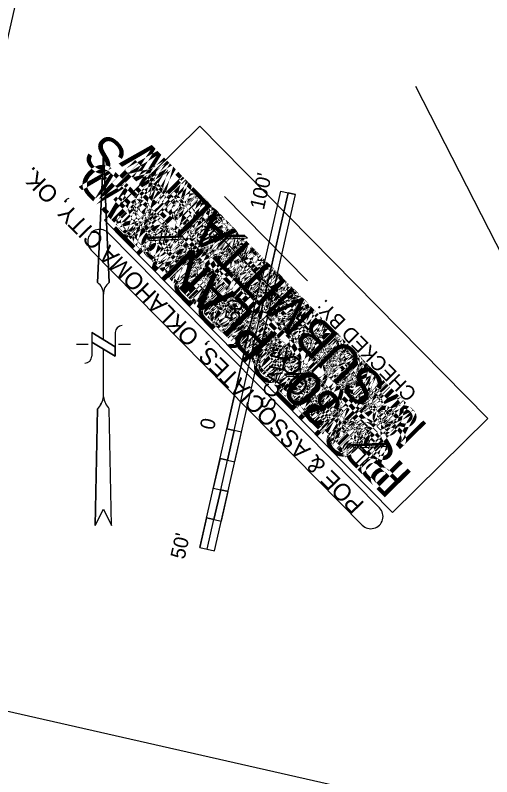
# Model space of a CAD drawing. Extents: x 2149833 to 2151401, y 143015 to 145036.
# Drawn here: x 2149999.9 to 2150195.2, y 143400.5 to 143713 of the extents above; entities that cross this region are included whole.
import ezdxf

# ---------------------------------------------------------------- set-up
doc = ezdxf.new("R2010")
doc.units = 0
for name, color, linetype in [('PR_Align_Ramp_A_Leader', 7, 'Continuous'), ('SHT_North_Arrow', 7, 'Continuous'), ('SHT_Scale', 7, 'Continuous'), ('SHT_Sheet_Border', 7, 'Continuous'), ('SHT_Stamp_30_Submit', 7, 'Continuous'), ('SHT_Stamp_70_Submit', 7, 'Continuous'), ('SHT_Stamp_Check_Print', 7, 'Continuous'), ('SHT_Stamp_Est_Inf', 7, 'Continuous'), ('SHT_Stamp_FFR', 7, 'Continuous'), ('SHT_Stamp_Info_Material', 7, 'Continuous'), ('SHT_Stamp_No_Const', 7, 'Continuous'), ('SHT_Stamp_No_Design', 7, 'Continuous'), ('SHT_Stamp_Plan_Hand', 7, 'Continuous'), ('SHT_Stamp_Pre_Plan', 7, 'Continuous'), ('SHT_Stamp_Ret_Sub', 7, 'Continuous'), ('SHT_Stamp_Rev_Prop_RW', 7, 'Continuous'), ('SHT_Stamp_Rev_Sheet', 7, 'Continuous'), ('SHT_Stamp_RW_Utilities_Meeting', 7, 'Continuous'), ('SHT_Stamp_RW_Utilities_Review', 7, 'Continuous'), ('SHT_Stamp_Send_Comments', 7, 'Continuous')]:
    doc.layers.add(name, color=color, linetype=linetype)

msp = doc.modelspace()

# ---------------------------------------------------------------- linework, layer by layer
at = {"layer": 'PR_Align_Ramp_A_Leader'}
msp.add_lwpolyline([(2150163.96, 143683.88), (2150268.72, 143479.12)], dxfattribs=at)
at = {"layer": 'SHT_North_Arrow'}
for p, q in [((2150033.65, 143603.23), (2150036.05, 143656.12)), ((2150036.05, 143656.12), (2150033.65, 143603.23)), ((2150036.05, 143656.12), (2150038.46, 143603.23)), ((2150038.46, 143603.23), (2150036.05, 143656.12)), ((2150036.05, 143579.84), (2150036.05, 143598.55)), ((2150040.85, 143576.96), (2150031.26, 143582.72)), ((2150031.26, 143582.72), (2150040.85, 143576.96)), ((2150031.26, 143582.72), (2150031.26, 143573.12)), ((2150036.05, 143579.84), (2150031.26, 143582.72)), ((2150031.26, 143582.72), (2150031.26, 143578.88)), ((2150040.85, 143582.72), (2150040.85, 143573.12)), ((2150040.85, 143573.12), (2150031.26, 143578.88)), ((2150040.85, 143576.96), (2150036.05, 143579.84)), ((2150029.82, 143577.92), (2150025.02, 143577.92)), ((2150036.05, 143556.33), (2150036.05, 143576)), ((2150040.85, 143573.12), (2150040.85, 143576.96)), ((2150047.09, 143577.92), (2150042.29, 143577.92)), ((2150032.69, 143503.56), (2150033.65, 143551.53)), ((2150033.65, 143551.53), (2150032.69, 143503.56)), ((2150039.41, 143503.56), (2150038.45, 143551.53)), ((2150039.41, 143503.56), (2150038.45, 143551.53)), ((2150032.69, 143503.56), (2150036.05, 143510.27)), ((2150032.69, 143503.56), (2150036.05, 143510.27)), ((2150036.05, 143510.27), (2150039.41, 143503.56)), ((2150036.05, 143510.27), (2150039.41, 143503.56))]:
    msp.add_line(p, q, dxfattribs=at)
for points in [[(2150031.26, 143578.88), (2150036.05, 143576), (2150040.85, 143573.12)], [(2150036.06, 143556.33), (2150036.05, 143556.33), (2150036.05, 143556.33)]]:
    msp.add_lwpolyline(points, dxfattribs=at)
for centre, radius, start, end in [((2150030.3, 143598.55), 5.76, 0, 54.3802), ((2150030.3, 143598.55), 5.76, 0, 54.3802), ((2150041.81, 143598.55), 5.76, 125.6198, 180), ((2150041.81, 143598.55), 5.76, 125.6198, 180), ((2150043.73, 143582.72), 2.88, 90, 180), ((2150028.38, 143573.12), 2.88, 270, 0), ((2150027.7, 143557.5), 8.43, 314.9567, 352.4189), ((2150027.7, 143557.5), 8.43, 314.9567, 352.059), ((2150044.4, 143557.5), 8.43, 187.5811, 225.0433), ((2150044.4, 143557.5), 8.43, 187.941, 225.0433)]:
    msp.add_arc(centre, radius, start, end, dxfattribs=at)
at = {"layer": 'SHT_Scale'}
for p, q in [((2150075.55, 143494.54), (2150108.75, 143640.82)), ((2150081.64, 143493.16), (2150114.84, 143639.44)), ((2150089.66, 143542.61), (2150111.8, 143640.13)), ((2150111.8, 143640.13), (2150100.73, 143591.37)), ((2150103.78, 143590.68), (2150114.84, 143639.44)), ((2150108.75, 143640.82), (2150111.8, 143640.13)), ((2150111.8, 143640.13), (2150114.84, 143639.44)), ((2150114.84, 143639.44), (2150111.8, 143640.13)), ((2150097.68, 143592.06), (2150086.61, 143543.3)), ((2150089.66, 143542.61), (2150100.73, 143591.37)), ((2150100.73, 143591.37), (2150097.68, 143592.06)), ((2150100.73, 143591.37), (2150097.68, 143592.06)), ((2150103.78, 143590.68), (2150100.73, 143591.37)), ((2150100.73, 143591.37), (2150103.78, 143590.68)), ((2150089.66, 143542.61), (2150086.61, 143543.3)), ((2150086.61, 143543.3), (2150089.66, 143542.61)), ((2150086.89, 143530.42), (2150089.66, 143542.61)), ((2150089.66, 143542.61), (2150086.89, 143530.42)), ((2150092.71, 143541.92), (2150089.66, 143542.61)), ((2150092.71, 143541.92), (2150089.66, 143542.61)), ((2150089.94, 143529.73), (2150092.71, 143541.92)), ((2150083.85, 143531.11), (2150081.08, 143518.92)), ((2150083.85, 143531.11), (2150089.94, 143529.73)), ((2150086.89, 143530.42), (2150083.85, 143531.11)), ((2150084.13, 143518.23), (2150086.89, 143530.42)), ((2150084.13, 143518.23), (2150086.89, 143530.42)), ((2150086.89, 143530.42), (2150089.94, 143529.73)), ((2150081.08, 143518.92), (2150087.18, 143517.54)), ((2150081.08, 143518.92), (2150087.18, 143517.54)), ((2150081.08, 143518.92), (2150084.13, 143518.23)), ((2150081.36, 143506.04), (2150084.13, 143518.23)), ((2150084.13, 143518.23), (2150081.36, 143506.04)), ((2150087.18, 143517.54), (2150084.13, 143518.23)), ((2150084.41, 143505.35), (2150087.18, 143517.54)), ((2150078.31, 143506.73), (2150075.55, 143494.54)), ((2150078.31, 143506.73), (2150084.41, 143505.35)), ((2150081.36, 143506.04), (2150078.31, 143506.73)), ((2150078.59, 143493.85), (2150081.36, 143506.04)), ((2150078.59, 143493.85), (2150081.36, 143506.04)), ((2150081.36, 143506.04), (2150084.41, 143505.35)), ((2150075.55, 143494.54), (2150081.64, 143493.16)), ((2150075.55, 143494.54), (2150078.59, 143493.85))]:
    msp.add_line(p, q, dxfattribs=at)
at = {"layer": 'SHT_Sheet_Border'}
msp.add_lwpolyline([(2151309.68, 144744.32), (2150961.07, 143208.38), (2149937.11, 143440.79), (2150285.72, 144976.72)], close=True, dxfattribs=at)
at = {"layer": 'SHT_Stamp_30_Submit'}
for p, q in [((2150075.62, 143667.47), (2150036.46, 143628.91)), ((2150193.7, 143547.55), (2150075.62, 143667.47)), ((2150154.53, 143508.99), (2150036.46, 143628.91)), ((2150149.25, 143510.8), (2150038.19, 143623.6)), ((2150142.12, 143503.79), (2150031.06, 143616.58)), ((2150121.9, 143566.24), (2150110.3, 143565.73)), ((2150122.17, 143565.96), (2150110.57, 143565.45)), ((2150122.97, 143565.15), (2150121.9, 143566.24)), ((2150111.37, 143564.64), (2150110.3, 143565.73)), ((2150122.35, 143565.79), (2150110.74, 143565.27)), ((2150122.97, 143565.15), (2150111.37, 143564.64)), ((2150193.7, 143547.55), (2150154.53, 143508.99))]:
    msp.add_line(p, q, dxfattribs=at)
for centre, start, end in [((2150034.6, 143620.09), 44.5567, 224.5615), ((2150145.67, 143507.29), 224.5519, 44.5567)]:
    msp.add_arc(centre, 5, start, end, dxfattribs=at)
at = {"layer": 'SHT_Stamp_70_Submit'}
for p, q in [((2150075.62, 143667.47), (2150036.46, 143628.91)), ((2150193.7, 143547.55), (2150075.62, 143667.47)), ((2150154.53, 143508.99), (2150036.46, 143628.91)), ((2150149.25, 143510.8), (2150038.19, 143623.6)), ((2150142.12, 143503.79), (2150031.06, 143616.58)), ((2150121.9, 143566.24), (2150110.3, 143565.73)), ((2150122.17, 143565.96), (2150110.57, 143565.45)), ((2150122.97, 143565.15), (2150121.9, 143566.24)), ((2150111.37, 143564.64), (2150110.3, 143565.73)), ((2150122.35, 143565.79), (2150110.74, 143565.27)), ((2150122.97, 143565.15), (2150111.37, 143564.64)), ((2150193.7, 143547.55), (2150154.53, 143508.99))]:
    msp.add_line(p, q, dxfattribs=at)
for centre, start, end in [((2150034.6, 143620.09), 44.5567, 224.5615), ((2150145.67, 143507.29), 224.5519, 44.5567)]:
    msp.add_arc(centre, 5, start, end, dxfattribs=at)
at = {"layer": 'SHT_Stamp_Check_Print'}
for p, q in [((2150075.62, 143667.47), (2150036.46, 143628.91)), ((2150193.7, 143547.55), (2150075.62, 143667.47)), ((2150119.74, 143603.96), (2150085.7, 143638.54)), ((2150154.53, 143508.99), (2150036.46, 143628.91)), ((2150110.64, 143595), (2150076.6, 143629.57)), ((2150149.25, 143510.8), (2150038.19, 143623.6)), ((2150142.12, 143503.79), (2150031.06, 143616.58)), ((2150193.7, 143547.55), (2150154.53, 143508.99))]:
    msp.add_line(p, q, dxfattribs=at)
for centre, start, end in [((2150034.6, 143620.09), 44.5567, 224.5615), ((2150145.67, 143507.29), 224.5519, 44.5567)]:
    msp.add_arc(centre, 5, start, end, dxfattribs=at)
at = {"layer": 'SHT_Stamp_Est_Inf'}
for p, q in [((2150075.62, 143667.47), (2150036.46, 143628.91)), ((2150193.7, 143547.55), (2150075.62, 143667.47)), ((2150154.53, 143509), (2150036.46, 143628.91)), ((2150149.24, 143510.8), (2150038.19, 143623.6)), ((2150142.12, 143503.79), (2150031.06, 143616.58)), ((2150193.7, 143547.55), (2150154.53, 143509))]:
    msp.add_line(p, q, dxfattribs=at)
for centre, start, end in [((2150034.6, 143620.09), 44.5567, 224.5615), ((2150145.67, 143507.29), 224.5519, 44.5567)]:
    msp.add_arc(centre, 5, start, end, dxfattribs=at)
at = {"layer": 'SHT_Stamp_FFR'}
for p, q in [((2150075.62, 143667.47), (2150036.46, 143628.91)), ((2150193.7, 143547.55), (2150075.62, 143667.47)), ((2150154.53, 143508.99), (2150036.46, 143628.91)), ((2150149.25, 143510.8), (2150038.19, 143623.6)), ((2150142.12, 143503.79), (2150031.06, 143616.58)), ((2150193.7, 143547.55), (2150154.53, 143508.99))]:
    msp.add_line(p, q, dxfattribs=at)
for centre, start, end in [((2150034.6, 143620.09), 44.5567, 224.5615), ((2150145.67, 143507.29), 224.5519, 44.5567)]:
    msp.add_arc(centre, 5, start, end, dxfattribs=at)
at = {"layer": 'SHT_Stamp_Info_Material'}
for p, q in [((2150075.62, 143667.47), (2150036.46, 143628.91)), ((2150193.7, 143547.55), (2150075.62, 143667.47)), ((2150154.53, 143508.99), (2150036.46, 143628.91)), ((2150149.25, 143510.8), (2150038.19, 143623.6)), ((2150142.12, 143503.79), (2150031.06, 143616.58)), ((2150193.7, 143547.55), (2150154.53, 143508.99))]:
    msp.add_line(p, q, dxfattribs=at)
for centre, start, end in [((2150034.6, 143620.09), 44.5567, 224.5615), ((2150145.67, 143507.29), 224.5519, 44.5567)]:
    msp.add_arc(centre, 5, start, end, dxfattribs=at)
at = {"layer": 'SHT_Stamp_No_Const'}
for p, q in [((2150075.62, 143667.47), (2150036.46, 143628.91)), ((2150193.7, 143547.55), (2150075.62, 143667.47)), ((2150154.53, 143508.99), (2150036.46, 143628.91)), ((2150149.25, 143510.8), (2150038.19, 143623.6)), ((2150142.12, 143503.79), (2150031.06, 143616.58)), ((2150193.7, 143547.55), (2150154.53, 143508.99))]:
    msp.add_line(p, q, dxfattribs=at)
for centre, start, end in [((2150034.6, 143620.09), 44.5567, 224.5615), ((2150145.67, 143507.29), 224.5519, 44.5567)]:
    msp.add_arc(centre, 5, start, end, dxfattribs=at)
at = {"layer": 'SHT_Stamp_No_Design'}
for p, q in [((2150075.62, 143667.47), (2150036.46, 143628.91)), ((2150193.7, 143547.55), (2150075.62, 143667.47)), ((2150154.53, 143508.99), (2150036.46, 143628.91)), ((2150149.25, 143510.8), (2150038.19, 143623.6)), ((2150142.12, 143503.79), (2150031.06, 143616.58)), ((2150193.7, 143547.55), (2150154.53, 143508.99))]:
    msp.add_line(p, q, dxfattribs=at)
for centre, start, end in [((2150034.6, 143620.09), 44.5567, 224.5615), ((2150145.67, 143507.29), 224.5519, 44.5567)]:
    msp.add_arc(centre, 5, start, end, dxfattribs=at)
at = {"layer": 'SHT_Stamp_Plan_Hand'}
for p, q in [((2150075.62, 143667.47), (2150036.46, 143628.91)), ((2150193.7, 143547.55), (2150075.62, 143667.47)), ((2150154.53, 143508.99), (2150036.46, 143628.91)), ((2150149.25, 143510.8), (2150038.19, 143623.6)), ((2150142.12, 143503.79), (2150031.06, 143616.58)), ((2150193.7, 143547.55), (2150154.53, 143508.99))]:
    msp.add_line(p, q, dxfattribs=at)
for centre, start, end in [((2150034.6, 143620.09), 44.5567, 224.5615), ((2150145.67, 143507.29), 224.5519, 44.5567)]:
    msp.add_arc(centre, 5, start, end, dxfattribs=at)
at = {"layer": 'SHT_Stamp_Pre_Plan'}
for p, q in [((2150075.62, 143667.47), (2150036.46, 143628.91)), ((2150193.7, 143547.55), (2150075.62, 143667.47)), ((2150154.53, 143508.99), (2150036.46, 143628.91)), ((2150149.25, 143510.8), (2150038.19, 143623.6)), ((2150142.12, 143503.79), (2150031.06, 143616.58)), ((2150193.7, 143547.55), (2150154.53, 143508.99))]:
    msp.add_line(p, q, dxfattribs=at)
for centre, start, end in [((2150034.6, 143620.09), 44.5567, 224.5615), ((2150145.67, 143507.29), 224.5519, 44.5567)]:
    msp.add_arc(centre, 5, start, end, dxfattribs=at)
at = {"layer": 'SHT_Stamp_Ret_Sub'}
for p, q in [((2150075.62, 143667.47), (2150036.46, 143628.91)), ((2150193.7, 143547.55), (2150075.62, 143667.47)), ((2150154.53, 143508.99), (2150036.46, 143628.91)), ((2150149.25, 143510.8), (2150038.19, 143623.6)), ((2150142.12, 143503.79), (2150031.06, 143616.58)), ((2150193.7, 143547.55), (2150154.53, 143508.99))]:
    msp.add_line(p, q, dxfattribs=at)
for centre, start, end in [((2150034.6, 143620.09), 44.5567, 224.5615), ((2150145.67, 143507.29), 224.5519, 44.5567)]:
    msp.add_arc(centre, 5, start, end, dxfattribs=at)
at = {"layer": 'SHT_Stamp_Rev_Prop_RW'}
for p, q in [((2150075.62, 143667.47), (2150036.46, 143628.91)), ((2150193.7, 143547.55), (2150075.62, 143667.47)), ((2150154.53, 143508.99), (2150036.46, 143628.91)), ((2150149.25, 143510.8), (2150038.19, 143623.6)), ((2150093.74, 143622.78), (2150079.41, 143622.15)), ((2150094.07, 143622.44), (2150079.75, 143621.8)), ((2150094.29, 143622.22), (2150079.96, 143621.58)), ((2150095.06, 143621.43), (2150093.74, 143622.78)), ((2150080.73, 143620.8), (2150079.41, 143622.15)), ((2150095.06, 143621.43), (2150080.73, 143620.8)), ((2150142.12, 143503.79), (2150031.06, 143616.58)), ((2150193.7, 143547.55), (2150154.53, 143508.99))]:
    msp.add_line(p, q, dxfattribs=at)
for centre, start, end in [((2150034.6, 143620.09), 44.5567, 224.5615), ((2150145.67, 143507.29), 224.5519, 44.5567)]:
    msp.add_arc(centre, 5, start, end, dxfattribs=at)
at = {"layer": 'SHT_Stamp_Rev_Sheet'}
for p, q in [((2150075.62, 143667.47), (2150036.46, 143628.91)), ((2150193.7, 143547.55), (2150075.62, 143667.47)), ((2150154.53, 143508.99), (2150036.46, 143628.91)), ((2150149.25, 143510.8), (2150038.19, 143623.6)), ((2150142.12, 143503.79), (2150031.06, 143616.58)), ((2150193.7, 143547.55), (2150154.53, 143508.99))]:
    msp.add_line(p, q, dxfattribs=at)
for centre, start, end in [((2150034.6, 143620.09), 44.5567, 224.5615), ((2150145.67, 143507.29), 224.5519, 44.5567)]:
    msp.add_arc(centre, 5, start, end, dxfattribs=at)
at = {"layer": 'SHT_Stamp_RW_Utilities_Meeting'}
for p, q in [((2150075.62, 143667.47), (2150036.46, 143628.91)), ((2150193.7, 143547.55), (2150075.62, 143667.47)), ((2150154.53, 143508.99), (2150036.46, 143628.91)), ((2150149.25, 143510.8), (2150038.19, 143623.6)), ((2150142.12, 143503.79), (2150031.06, 143616.58)), ((2150193.7, 143547.55), (2150154.53, 143508.99)), ((2150151.95, 143537.31), (2150137.63, 143536.68)), ((2150138.95, 143535.33), (2150137.63, 143536.68)), ((2150152.29, 143536.97), (2150137.97, 143536.33)), ((2150152.51, 143536.75), (2150138.18, 143536.11)), ((2150153.28, 143535.96), (2150138.95, 143535.33)), ((2150153.28, 143535.96), (2150151.95, 143537.31))]:
    msp.add_line(p, q, dxfattribs=at)
for centre, start, end in [((2150034.6, 143620.09), 44.5567, 224.5615), ((2150145.67, 143507.29), 224.5519, 44.5567)]:
    msp.add_arc(centre, 5, start, end, dxfattribs=at)
at = {"layer": 'SHT_Stamp_RW_Utilities_Review'}
for p, q in [((2150075.62, 143667.47), (2150036.46, 143628.91)), ((2150193.7, 143547.55), (2150075.62, 143667.47)), ((2150154.53, 143508.99), (2150036.46, 143628.91)), ((2150149.25, 143510.8), (2150038.19, 143623.6)), ((2150068.15, 143622.41), (2150053.83, 143621.78)), ((2150069.48, 143621.07), (2150068.15, 143622.41)), ((2150055.15, 143620.43), (2150053.83, 143621.78)), ((2150068.49, 143622.07), (2150054.17, 143621.44)), ((2150068.71, 143621.85), (2150054.38, 143621.22)), ((2150069.48, 143621.07), (2150055.15, 143620.43)), ((2150142.12, 143503.79), (2150031.06, 143616.58)), ((2150193.7, 143547.55), (2150154.53, 143508.99))]:
    msp.add_line(p, q, dxfattribs=at)
for centre, start, end in [((2150034.6, 143620.09), 44.5567, 224.5615), ((2150145.67, 143507.29), 224.5519, 44.5567)]:
    msp.add_arc(centre, 5, start, end, dxfattribs=at)
at = {"layer": 'SHT_Stamp_Send_Comments'}
for p, q in [((2150075.62, 143667.47), (2150036.46, 143628.91)), ((2150193.7, 143547.55), (2150075.62, 143667.47)), ((2150154.53, 143508.99), (2150036.46, 143628.91)), ((2150149.25, 143510.8), (2150038.19, 143623.6)), ((2150142.12, 143503.79), (2150031.06, 143616.58)), ((2150193.7, 143547.55), (2150154.53, 143508.99))]:
    msp.add_line(p, q, dxfattribs=at)
for centre, start, end in [((2150034.6, 143620.09), 44.5567, 224.5615), ((2150145.67, 143507.29), 224.5519, 44.5567)]:
    msp.add_arc(centre, 5, start, end, dxfattribs=at)

# ---------------------------------------------------------------- texts
at = {"layer": 'SHT_Scale'}
for s, p in [("100'", (2150101.81, 143632.86)), ("50'", (2150091.4, 143586.97)), ('SCALE', (2150105.92, 143550.44)), ('0', (2150081.3, 143542.48)), ("50'", (2150069.26, 143489.45))]:
    msp.add_text(s, height=6, rotation=77.2123, dxfattribs=at).set_placement(p)
at = {"layer": 'SHT_Stamp_30_Submit'}
for s, height, p in [('POE & ASSOCIATES, OKLAHOMA CITY, OK.', 7, (2150143.34, 143512.71)), ('SUBMITTAL', 15, (2150152.73, 143561.33)), ('30   PLAN', 15, (2150135.07, 143553.14)), ('O', 7.65, (2150118.83, 143569.32)), ('O', 7.65, (2150121.16, 143560.95))]:
    msp.add_text(s, height=height, rotation=134.5567, dxfattribs=at).set_placement(p)
at = {"layer": 'SHT_Stamp_70_Submit'}
for s, height, p in [('POE & ASSOCIATES, OKLAHOMA CITY, OK.', 7, (2150143.34, 143512.71)), ('SUBMITTAL', 15, (2150152.73, 143561.33)), ('70   PLAN', 15, (2150135.32, 143552.88)), ('O', 7.65, (2150118.83, 143569.32)), ('O', 7.65, (2150121.16, 143560.95))]:
    msp.add_text(s, height=height, rotation=134.5567, dxfattribs=at).set_placement(p)
at = {"layer": 'SHT_Stamp_Check_Print'}
for s, height, p in [('POE & ASSOCIATES, OKLAHOMA CITY, OK.', 7, (2150143.33, 143512.71)), ('CHECK PRINT', 15, (2150145.79, 143539.16)), ('CHECKED BY:', 6, (2150164.91, 143558.08)), ('REVISED BY:', 6, (2150155.83, 143549.13))]:
    msp.add_text(s, height=height, rotation=134.5567, dxfattribs=at).set_placement(p)
at = {"layer": 'SHT_Stamp_Est_Inf'}
for s, height, p in [('POE & ASSOCIATES, OKLAHOMA CITY, OK.', 7, (2150143.33, 143512.71)), ('INFORMATION', 15, (2150160.4, 143553.54)), ('BASED ON EST.', 15, (2150151.6, 143536.35))]:
    msp.add_text(s, height=height, rotation=134.5567, dxfattribs=at).set_placement(p)
at = {"layer": 'SHT_Stamp_FFR'}
for s, height, p in [('POE & ASSOCIATES, OKLAHOMA CITY, OK.', 7, (2150143.33, 143512.71)), ('FINAL FIELD', 15, (2150143.85, 143544.21)), ('REVIEW', 15, (2150141.92, 143572.31))]:
    msp.add_text(s, height=height, rotation=134.5567, dxfattribs=at).set_placement(p)
at = {"layer": 'SHT_Stamp_Info_Material'}
for s, height, p in [('MATERIAL ONLY', 15, (2150169.47, 143544.33)), ('POE & ASSOCIATES, OKLAHOMA CITY, OK.', 7, (2150143.33, 143512.71)), ('INFORMATION', 15, (2150147.33, 143540.68))]:
    msp.add_text(s, height=height, rotation=134.5567, dxfattribs=at).set_placement(p)
at = {"layer": 'SHT_Stamp_No_Const'}
for s, height, p in [('POE & ASSOCIATES, OKLAHOMA CITY, OK.', 7, (2150143.33, 143512.71)), ('NOT TO BE USED', 15, (2150158.27, 143529.57)), ('FOR CONST.', 15, (2150154.14, 143559.9))]:
    msp.add_text(s, height=height, rotation=134.5567, dxfattribs=at).set_placement(p)
at = {"layer": 'SHT_Stamp_No_Design'}
for s, height, p in [('POE & ASSOCIATES, OKLAHOMA CITY, OK.', 7, (2150143.33, 143512.71)), ('NOT TO BE USED', 15, (2150158.27, 143529.57)), ('FOR DESIGN', 15, (2150154.76, 143559.27))]:
    msp.add_text(s, height=height, rotation=134.5567, dxfattribs=at).set_placement(p)
at = {"layer": 'SHT_Stamp_Plan_Hand'}
for s, height, p in [('POE & ASSOCIATES, OKLAHOMA CITY, OK.', 7, (2150143.33, 143512.71)), ('PLAN-IN-HAND', 15, (2150156.27, 143544.67))]:
    msp.add_text(s, height=height, rotation=134.5567, dxfattribs=at).set_placement(p)
at = {"layer": 'SHT_Stamp_Pre_Plan'}
for s, height, p in [('POE & ASSOCIATES, OKLAHOMA CITY, OK.', 7, (2150143.33, 143512.71)), ('PRELIMINARY', 15, (2150146.79, 143541.23)), ('PLANS', 15, (2150138.56, 143575.72))]:
    msp.add_text(s, height=height, rotation=134.5567, dxfattribs=at).set_placement(p)
at = {"layer": 'SHT_Stamp_Ret_Sub'}
for s, height, p in [('POE & ASSOCIATES, OKLAHOMA CITY, OK.', 7, (2150143.33, 143512.71)), ('RET. SUBMITTED', 15, (2150152.06, 143535.88)), ('MATERIALS', 15, (2150153.15, 143560.91))]:
    msp.add_text(s, height=height, rotation=134.5567, dxfattribs=at).set_placement(p)
at = {"layer": 'SHT_Stamp_Rev_Prop_RW'}
for s, height, p in [('PROPOSED R W', 15, (2150163.96, 143549.92)), ('POE & ASSOCIATES, OKLAHOMA CITY, OK.', 7, (2150143.33, 143512.71)), ('REVISED', 15, (2150130.35, 143557.93))]:
    msp.add_text(s, height=height, rotation=134.5567, dxfattribs=at).set_placement(p)
at = {"layer": 'SHT_Stamp_Rev_Sheet'}
for s, height, p in [('REVISED SHEET', 15, (2150158.01, 143542.9)), ('POE & ASSOCIATES, OKLAHOMA CITY, OK.', 7, (2150143.33, 143512.71))]:
    msp.add_text(s, height=height, rotation=134.5567, dxfattribs=at).set_placement(p)
at = {"layer": 'SHT_Stamp_RW_Utilities_Meeting'}
for s, height, p in [('POE & ASSOCIATES, OKLAHOMA CITY, OK.', 7, (2150143.34, 143512.71)), ('R W & UTILITIES', 15, (2150159.89, 143527.93)), ('MEETING', 15, (2150145.98, 143568.19))]:
    msp.add_text(s, height=height, rotation=134.5567, dxfattribs=at).set_placement(p)
at = {"layer": 'SHT_Stamp_RW_Utilities_Review'}
for s, height, p in [('& UTIL.  REVIEW', 15, (2150166.36, 143547.48)), ('POE & ASSOCIATES, OKLAHOMA CITY, OK.', 7, (2150143.34, 143512.71)), ('PRELIMINARY R W', 15, (2150163.24, 143524.52))]:
    msp.add_text(s, height=height, rotation=134.5567, dxfattribs=at).set_placement(p)
at = {"layer": 'SHT_Stamp_Send_Comments'}
for s, height, p in [('SEND COMMENTS', 15, (2150162.52, 143538.32)), ('POE & ASSOCIATES, OKLAHOMA CITY, OK.', 7, (2150143.33, 143512.71))]:
    msp.add_text(s, height=height, rotation=134.5567, dxfattribs=at).set_placement(p)

doc.saveas('drawing.dxf')
